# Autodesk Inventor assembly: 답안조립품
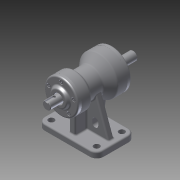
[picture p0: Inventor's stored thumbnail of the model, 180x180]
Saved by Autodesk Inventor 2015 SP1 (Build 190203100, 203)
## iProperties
Created: 2015-08
Part Number: 답안조립품
Document SubType Name: Assembly
Designer: jun
Author: jun
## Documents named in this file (10)
- C:\Users\jun\Desktop\450805V1023\답안조립품.iam
- C:\Users\jun\Desktop\450805V1023\본체.ipt
- C:\Users\jun\Desktop\450805V1023\축.ipt
- C:\Users\jun\Desktop\450805V1023\앞커버.ipt
- C:\Users\jun\Desktop\450805V1023\뒤커버.ipt
- C:\Users\jun\Desktop\450805V1023\베어링 6203.ipt
- C:\Users\jun\Desktop\450805V1023\베어링 6205.ipt
- C:\Users\jun\Desktop\450805V1023\오일실 .ipt
- 오일실 .ipt
- C:\Users\jun\Desktop\450805V1023\M4x0.5.ipt
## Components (10 placed, 1 different names)
1. M4x0.5:1
2. M4x0.5:2
3. M4x0.5:3
4. M4x0.5:4
5. M4x0.5:5
6. M4x0.5:6
7. M4x0.5:7
8. M4x0.5:8
9. M4x0.5:9
10. M4x0.5:10
